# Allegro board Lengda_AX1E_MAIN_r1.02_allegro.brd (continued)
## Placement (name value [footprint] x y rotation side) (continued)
PC68  10UF  [CC0603N]  176.43 94.46 315 top
PC69  4.7UF  [CC0603N]  95.68 88.14 0 top
PCP2  47uF  [CAE660W800HN]  167.18 111.65 90 top
PR1  0  [RC0603N]  198.93 105.7 180 top
PR2  1.1K  [RC0402N]  225.47 112.56 90 bottom
PR3  0  [RC0402N]  219.22 106.13 180 bottom
PR4  2.2  [RC0603N]  230.4 105.34 0 bottom
PR5  10k  [RC0402N]  196.62 106.59 0 top
PR6  10k  [RC0402N]  219.23 105.35 180 bottom
PR7  110K  [RC0402N]  223.54 91.15 270 bottom
PR8  6.2K  [RC0402N]  224.3 91.15 270 bottom
PR9  30K  [RC0402N]  225.29 91.28 270 bottom
PR10  2.2  [RC0603N]  208.49 103.12 180 bottom
PR11  0  [RC0402N]  208.57 105.26 180 bottom
PR12  2.2  [RC0603N]  203.51 106.36 180 bottom
PR13  100  [RC0402N]  154.29 44.92 180 bottom
PR14  2.2  [RC0805N]  196.63 111.68 270 top
PR15  2.2  [RC0603N]  230.55 99.16 0 bottom
PR16  0  [RC0603N]  190.63 113.81 0 top
PR17  100k  [RC0402N]  228.87 108.58 0 bottom
PR21  560  [RC0402N]  223.12 96.67 270 bottom
PR22  1k  [RC0402N]  190.72 114.8 0 top
PR24  3.9K  [RC0402N]  225.15 96.71 270 bottom
PR25  3K  [RC0402N]  223.38 108.13 90 bottom
PR26  360  [RC0402N]  224.16 96.68 270 bottom
PR28  1.1K  [RC0402N]  222.72 106.81 180 bottom
PR29  20K  [RC0402N]  160.89 79.39 180 top
PR30  20K  [RC0402N]  160.88 80.15 0 top
PR31  1.1K  [RC0402N]  222.07 108.24 270 bottom
PR32  2.2  [RC0603N]  167.06 100.07 270 bottom
PR33  16K  [RC0402N]  223.12 94.9 270 bottom
PR34  5.6K  [RC0402N]  224.15 94.88 270 bottom
PR35  22K  [RC0402N]  225.16 94.92 270 bottom
PR36  2.2  [RC0603N]  158.38 111.1 180 top
PR37  20K  [RC0402N]  162.19 79.36 270 top
PR38  10k  [RC0402N]  158.11 110 180 top
PR39  2.2  [RC0805N]  153.57 102.25 0 top
PR40  0_F  [RC0603N]  161.39 110.64 0 top
PR41  2.2  [RC0603N]  229.06 109.67 0 bottom
PR43  0  [RC0603N]  180.88 110.53 180 top
PR44  10k  [RC0402N]  179.08 110 90 top
PR45  1.1K  [RC0402N]  216.6 109.26 270 bottom
PR46  1.1K  [RC0402N]  224.44 112.42 270 bottom
PR47  2.2  [RC0805N]  177.81 104.05 0 top
PR48  0  [RC0603N]  182.48 113.36 270 top
PR49  3K  [RC0402N]  217.43 110.23 90 bottom
PR50  1k  [RC0402N]  182.2 111.61 0 top
PR51  0  [RC0402N]  214.94 104.09 180 bottom
PR52  10k  [RC0402N]  216.3 104.19 90 bottom
PR53  27K  [RC0402N]  217.87 104.19 270 bottom
PR54  1.1K  [RC0402N]  218.21 110.23 270 bottom
PR55  100  [RC0402N]  215.58 78.18 180 bottom
PR56  20K  [RC0402N]  162.97 79.37 90 top
PR57  1k  [RC0402N]  161.84 111.66 180 top
PR58  820  [RC0402N]  159.2 98.43 90 bottom
PR59  100  [RC0402N]  218.75 101.61 0 bottom
PR60  120  [RC0402N]  157.58 98.42 270 bottom
PR61  0  [RC0402N]  161.91 101.95 270 bottom
PR62  10k  [RC0402N]  160.01 101.73 270 bottom
PR63  10k  [RC0402N]  157.78 102.86 0 bottom
PR64  100  [RC0402N]  161.11 101.95 270 bottom
PR65  0  [RC0603N]  210.97 114.35 270 top
PR66  0  [RC0402N]  164.19 99.71 270 bottom
PR67  10k  [RC0402N]  210.97 112.61 180 top
PR68  10k  [RC0402N]  230.76 106.38 180 bottom
PR69  100  [RC0402N]  163.4 99.71 90 bottom
PR70  100  [RC0402N]  214.94 103.32 180 bottom
PR71  100  [RC0402N]  154.61 55.8 270 bottom
PR72  75  [RC0402N]  66.87 77.48 270 bottom
PR73  2.2  [RC0805N]  208.3 104.06 90 top
PR74  0  [RC0603N]  212.76 113.63 270 top
PR75  75  [RC0402N]  67.75 82.66 90 bottom
PR76  75  [RC0402N]  67.66 77.49 270 bottom
PR77  10k  [RC0402N]  221.64 97.68 180 bottom
PR78  2.2  [RC0603N]  230.38 102.87 180 bottom
PR79  3K  [RC0402N]  223.65 112.43 270 bottom
PR80  1k  [RC0402N]  213.75 113.92 270 top
PR81  3.9  [RC0402N]  218.75 100.82 0 bottom
PR83  100  [RC0402N]  212.4 78.15 180 bottom
PR92  0_F  [RC0603N]  111.63 57.86 90 bottom
PR93  10k  [RC0402N]  227.95 98.93 180 bottom
PR94  15K  [RC0402N]  225.68 110.91 0 bottom
PR95  110K  [RC0402N]  225.49 107.5 180 bottom
PR96  100K_NTC  [RC0402N]  201.32 105.79 0 top
PR97  18K  [RC0402N]  225.52 108.28 180 bottom
PR98  6.8  [RC0603N]  218.16 98.41 0 bottom
PR100  100K_NTC  [RC0402N]  188.16 101.76 90 top
PR101  8.06K  [RC0402N]  216.95 99.62 180 bottom
PR102  10k  [RC0402N]  216.94 100.55 180 bottom
PR103  12.7K  [RC0402N]  215.63 100.14 270 bottom
PR106  0  [RC0402N]  218.76 102.39 180 bottom
PR107  1k  [RC0402N]  44.91 13.36 90 bottom
PR108  6.34K  [RC0402N]  158.7 101.23 0 bottom
PR109  0  [RC0402N]  223.2 93.11 270 bottom
PR110  360  [RC0402N]  224.2 93.11 270 bottom
PR111  2.2K  [RC0402N]  225.16 93.11 270 bottom
PR112  0  [RC0402N]  219.19 103.39 0 bottom
PR113  0  [RC0402N]  218.75 100.04 180 bottom
PR114  100_R  [RC0402N]  225.19 109.59 90 bottom
PR115  150  [RC0402N]  226 109.62 270 bottom
PR116  0  [RC0402N]  160.02 97.06 180 bottom
PR117  0  [RC0402N]  160.49 97.97 180 bottom
PR118  82  [RC0402N]  158.19 97.1 0 bottom
PR119  1k  [RC0402N]  165.3 103.6 0 top
PR120  1k  [RC0402N]  35.19 15.75 180 bottom
PU3  RT9610CQW  [DFN50P200X200-8CN]  205.7 104.5 180 bottom
Q1  SM2300NSANC  [SOT95P280-3N]  62.7 87.17 180 bottom
Q2  SM2300NSANC  [SOT95P280-3N]  62.7 90.53 180 bottom
Q4  BSS138  [SOT95P280-3N]  106.02 51.19 0 bottom
Q5  SM4370  [SOIC127P605X520-8N]  200.96 109.24 0 top
Q6  SM4373  [SOIC127P605X520-8N]  192.83 109.68 270 top
Q7  2N7002LT1  [SOT95P240-3N]  153.46 47.84 270 bottom
Q8  SM4370  [SOIC127P605X520-8N]  175.23 108.57 180 top
Q9  SM4373  [SOIC127P605X520-8N]  186 109.67 270 top
Q10  2N7002LT1  [SOT95P240-3N]  153.27 52.09 90 bottom
Q11  SM2300NSANC  [SOT95P280-3N]  52.08 84.84 270 bottom
Q12  2N7002LT1  [SOT95P240-3N]  52.19 72.43 90 top
Q13  2N7002LT1  [SOT95P240-3N]  48.81 72.43 90 top
Q14  LBSS138LT1G  [SOT95P240-3N]  61.53 81.99 90 top
Q15  2N7002LT1  [SOT95P240-3N]  148.92 56.97 0 top
Q17  AON3419  [DFN65P280X290-8N]  97.58 108.62 90 top
Q18  BSS138  [SOT95P280-3N]  148.7 53.57 180 top
Q19  2N7002LT1  [SOT95P240-3N]  156.46 70.26 0 top
Q22  SM4370  [SOIC127P605X520-8N]  153.6 106.15 180 top
Q23  SM4373  [SOIC127P605X520-8N]  160.92 106.56 180 top
Q27  2N7002LT1  [SOT95P240-3N]  156.46 73.6 0 top
Q29  SM4370  [SOIC127P605X520-8N]  207.82 109.25 180 top
Q30  2N7002LT1  [SOT95P240-3N]  95.52 109.03 270 bottom
Q31  2N7002LT1  [SOT95P240-3N]  83.47 107.56 90 top
Q32  SM4373  [SOIC127P605X520-8N]  214.36 108.74 270 top
Q34  APM1105NUCT-TRG  [SOT229P990-3N]  65.88 37.04 270 top
Q36  sc-70  [SOT65P210-3N]  121.46 113.07 90 top
Q40  SM2300NSANC  [SOT95P280-3N]  112.74 59.13 90 top
Q41  BSS138  [SOT95P280-3N]  35.1 56.55 90 top
Q42  2N7002LT1  [SOT95P240-3N]  65.09 22.63 180 bottom
Q44  2N7002LT1  [SOT95P240-3N]  34.61 60.7 90 top
Q48  L2N7002LT1G  [SOT_23_M]  43.86 87.1 270 bottom
Q49  LMBT3904LT1G  [SOT_23_M]  39.99 86.97 180 bottom
Q56  APM3302QA  [SON65P330X330-8N]  122.09 71.16 90 bottom
Q68  APM3302QA  [SON65P330X330-8N]  88.65 73.07 90 top
Q69  2N7002LT1  [SOT95P240-3N]  116.77 65.63 90 bottom
Q71  2N7002LT1  [SOT95P240-3N]  120.12 65.63 270 bottom
Q72  DTC144EUA  [SOT65P210-3N]  231.54 17.53 0 top
Q74  APM3302QA  [SON65P330X330-8N]  122.85 76.2 90 bottom
Q76  2N7002LT1  [SOT95P240-3N]  117.95 77.48 270 bottom
Q77  2N7002LT1  [SOT95P240-3N]  80.09 73.85 90 top
Q78  2N7002LT1  [SOT95P240-3N]  144.23 60.01 270 bottom
Q79  2N7002LT1  [SOT95P240-3N]  80.09 69.94 90 top
Q80  2N7002LT1  [SOT95P240-3N]  84.74 70.38 270 top
Q81  2N7002LT1  [SOT95P240-3N]  128.73 64.87 180 bottom
Q83  2N7002LT1  [SOT95P240-3N]  105.88 54.59 0 bottom
Q84  2N7002LT1  [SOT95P240-3N]  150.14 87.11 0 bottom
Q85  2N7002LT1  [SOT95P240-3N]  231.65 100.83 270 top
Q86  2N7002LT1  [SOT95P240-3N]  117.58 72.42 90 bottom
Q88  2N7002LT1  [SOT95P240-3N]  143.96 92.83 270 bottom
R1  2.2  [RC0603N]  118.31 53.85 0 bottom
R3  100k  [RC0402N]  176.37 63.28 90 bottom
R4  0  [RC0402N]  129.14 102.81 0 top
R5  10_F  [RC0603N]  144.21 97.29 90 top
R6  2.2  [RC0603N]  145.82 102.07 180 top
R7  10k  [RC0402N]  172.19 82.07 270 bottom
R8  100k  [RC0402N]  161.88 70.61 270 top
R9  2.2K  [RC0402N]  157.21 79.09 180 top
R10  2.2K  [RC0402N]  157.21 78.32 180 top
R11  0  [RC0402N]  153.3 79.95 0 top
R12  100k  [RC0402N]  158.76 69.26 270 top
R13  0_F  [RC0603N]  47.78 83.48 270 bottom
R14  0  [RC0402N]  31.69 53.36 90 bottom
R15  0  [RC0402N]  39.93 80.87 90 bottom
R16  100k  [RC0402N]  161.1 70.61 270 top
R17  200K  [RC0402N]  165.19 83.74 0 top
R18  150  [RC0402N]  197.9 88.04 0 top
R19  100k  [RC0402N]  170.1 57.28 0 bottom
R20  60.4  [RC0402N]  168.79 88.52 90 top
R21  10M  [RC0402N]  171.14 59.27 90 bottom
R22  1k  [RC0402N]  165.12 59.68 0 top
R23  150  [RC0402N]  209.51 85.6 0 bottom
R24  0  [RC0402N]  153.29 80.73 0 top
R25  20K  [RC0402N]  166.38 64.78 180 bottom
R26  33_R  [RC0402N]  152.55 54.26 0 top
R27  20K  [RC0402N]  166.09 58.14 270 bottom
R28  100k  [RC0402N]  175.59 63.29 90 bottom
R29  0  [RC0402N]  66.95 82.66 90 bottom
R30  100k  [RC0402N]  163.25 71.2 0 top
R31  100k  [RC0402N]  165.14 57.69 0 top
R32  100_R  [RC0402N]  227.44 94.49 270 bottom
R33  10_F  [RC0603N]  88.51 87.81 180 top
R34  10k  [RC0402N]  93.38 89.74 270 top
R35  10_F  [RC0603N]  126.16 79.71 270 top
R36  100k  [RC0402N]  125.85 77.31 270 top
R37  10k  [RC0402N]  121.14 77.31 90 top
R38  2.2  [RC0603N]  123.94 75.81 0 top
R39  13.7K  [RC0402N]  122.74 77.31 90 top
R40  61.9k  [RC0402N]  124.29 77.31 270 top
R41  49.9  [RC0402N]  207.38 84.74 90 bottom
R42  1.8K  [RC0603N]  197.91 20.28 180 bottom
R43  2  [RC0402N]  218.24 63.69 180 bottom
R44  0  [RC0402N]  218.45 55.15 90 bottom
R45  2  [RC0402N]  215.67 65.19 0 bottom
R46  0  [RC0603N]  153.32 57.28 90 bottom
R47  0  [RC0603N]  152.07 57.28 90 bottom
R48  0_F  [RC0603N]  58.24 72.87 180 bottom
R49  2.2K  [RC0402N]  155.44 79.56 90 top
R50  0  [RC0603N]  169.09 69.12 0 bottom
R51  0  [RC0603N]  169.02 70.37 0 bottom
R52  0  [RC0603N]  167.9 75.24 0 bottom
R53  0  [RC0603N]  167.1 78.77 0 bottom
R54  100k  [RC0402N]  175.71 68.63 90 bottom
R55  270K  [RC0402N]  114.55 57.38 270 bottom
R56  1k  [RC0402N]  112.62 57.38 90 bottom
R57  2.2K  [RC0402N]  155.44 77.77 270 top
R58  2.2K  [RC0402N]  164.05 78.56 270 top
R59  0_F  [RC0603N]  220.63 32.26 0 bottom
R62  0  [RC0402N]  220.91 33.27 180 bottom
R65  49.9  [RC0402N]  226.03 95.12 90 bottom
R66  0  [RC0402N]  177.44 74.39 90 bottom
R67  100_R  [RC0402N]  169.57 88.52 90 top
R68  0  [RC0402N]  179.22 57.29 225 top
R69  100k  [RC0402N]  165.14 58.87 0 top
R70  100k  [RC0402N]  110.92 56.07 180 bottom
R71  1M  [RC0402N]  165.92 65.61 0 bottom
R72  10k  [RC0402N]  165.85 69.2 180 top
R73  10k  [RC0402N]  165.76 80.61 180 top
R74  0  [RC0402N]  209.21 68.53 180 bottom
R75  100_R  [RC0402N]  219.73 61.86 180 top
R76  100_R  [RC0402N]  219.74 60.99 180 top
R77  100_R  [RC0402N]  219.7 62.57 180 top
R78  10k  [RC0402N]  165.84 69.98 180 top
R79  100_R  [RC0402N]  58.16 71.82 0 bottom
R80  49.9  [RC0402N]  183.48 66.26 270 bottom
R81  24.9  [RC0402N]  216.62 62.41 90 bottom
R82  0  [RC0402N]  42.61 80.1 90 bottom
R83  0  [RC0402N]  157.19 66.17 180 top
R84  10k  [RC0402N]  58.54 68.54 180 bottom
R85  49.9  [RC0402N]  167.99 88.53 90 top
R86  10k  [RC0402N]  58.54 67.74 180 bottom
R87  24.9  [RC0402N]  215.67 66.79 0 bottom
R88  10k  [RC0402N]  49.12 80.66 270 bottom
R90  0  [RC0402N]  40.18 58.74 270 bottom
R91  0  [RC0402N]  42.33 58.86 270 bottom
R92  10k  [RC0402N]  163.3 75.72 180 top
R93  100k  [RC0402N]  165.13 62.19 0 top
R94  100k  [RC0402N]  165.75 60.81 270 bottom
R96  0  [RC0402N]  176.95 76.59 270 bottom
R97  10k  [RC0402N]  165.14 56.88 0 top
R98  1k  [RC0402N]  184.01 90.09 270 top
R99  100k  [RC0402N]  178.32 70.74 270 bottom
R101  0  [RC0402N]  169.36 62.42 0 bottom
R102  60.4  [RC0402N]  184.81 90.1 270 top
R103  0  [RC0402N]  175.61 60.24 225 top
R104  4.7K  [RC0402N]  169.02 59.45 90 bottom
R105  10k  [RC0402N]  49.91 80.66 270 bottom
R106  1k  [RC0402N]  193.16 89.59 270 top
R107  4.7K  [RC0402N]  168.21 59.44 270 bottom
R108  100k  [RC0402N]  162.75 57.47 180 top
R109  1M  [RC0402N]  110.92 55.06 180 bottom
R110  100k  [RC0402N]  170.84 77.32 0 bottom
R111  100k  [RC0402N]  158.33 77.38 0 top
R112  0  [RC0402N]  110.92 54.29 0 bottom
R113  33_R  [RC0402N]  50.85 86.41 0 top
R114  1k  [RC0402N]  205.08 85.22 90 bottom
R115  10k  [RC0402N]  51.73 70.08 0 top
R116  10k  [RC0402N]  49.93 70.08 180 top
R117  0  [RC0402N]  110.92 51.96 180 bottom
R118  0  [RC0402N]  110.92 52.73 180 bottom
R119  100k  [RC0402N]  48.07 70.08 180 top
R120  0  [RC0402N]  110.92 53.51 180 bottom
R121  20K  [RC0402N]  112.89 50.29 90 bottom
R122  1k  [RC0402N]  218.89 85.84 0 bottom
R123  12K  [RC0603N]  111.13 49.82 180 bottom
R124  1k  [RC0402N]  219.19 88.69 270 top
R125  0  [RC0402N]  181.76 58.87 225 top
R126  0  [RC0402N]  58.54 69.32 180 bottom
R127  2.2  [RC0603N]  109.15 49.97 270 bottom
R128  0_F  [RC0603N]  206.65 32.22 0 bottom
R129  49.9  [RC0402N]  215.81 88.8 270 top
R130  0  [RC0402N]  58.54 66.95 180 bottom
R131  51  [RC0402N]  213.9 88.94 90 top
R132  51  [RC0402N]  210.88 85.99 270 bottom
R133  51  [RC0402N]  215.58 90.65 90 top
R134  0  [RC2512N]  97.46 108.48 90 top
R135  51  [RC0402N]  210.56 84.53 0 bottom
R137  51  [RC0402N]  214.79 88.81 90 top
R138  10k  [RC0402N]  51.05 80.74 270 bottom
R139  100k  [RC0402N]  162 98.04 90 bottom
R140  10k  [RC0402N]  51.84 80.74 270 bottom
R141  51  [RC0402N]  214.55 90.75 90 top
R142  0  [RC0402N]  182.21 57.88 225 top
R143  0  [RC0402N]  180.57 56.99 225 top
R144  0  [RC0402N]  181.2 56.36 225 top
R145  0  [RC0402N]  143.29 86.06 0 top
R146  1k  [RC0402N]  197.34 89.59 270 top
R147  1k  [RC0402N]  198.93 89.59 270 top
R148  1k  [RC0402N]  198.12 89.59 90 top
R149  1k  [RC0402N]  194.08 89.59 270 top
R150  0  [RC0402N]  163.09 60.16 180 top
R151  499  [RC0402N]  218.91 86.67 180 bottom
R153  51  [RC0402N]  208.87 90.36 270 bottom
R154  100k  [RC0402N]  177.89 63.45 90 bottom
R155  33_R  [RC0402N]  53.4 86.42 0 top
R156  100k  [RC0402N]  164.18 82.29 0 top
R157  0  [RC0402N]  57.77 76.22 180 top
R158  0  [RC0402N]  129.14 102.02 0 top
R159  1k  [RC0402N]  194.96 89.59 90 top
R160  10k  [RC0402N]  163.25 70.41 180 top
R161  0  [RC0402N]  129.14 101.02 0 top
R162  10k  [RC0402N]  165.85 70.91 0 top
R163  200  [RC0402N]  165.87 71.75 0 top
R164  0  [RC0402N]  129.14 100.17 0 top
R165  10k  [RC0402N]  58.55 70.9 180 bottom
R166  0  [RC0402N]  129.14 99.38 0 top
R167  0_F  [RC0603N]  206.66 33.45 0 bottom
R168  100_R  [RC0402N]  47.82 79.97 270 bottom
R169  1k  [RC0402N]  191.58 89.58 270 top
R170  390K  [RC0603N]  88.68 108.89 0 top
R171  100  [RC1206N]  94.46 113.41 0 top
R172  10k  [RC0603N]  85.72 108.64 90 top
R173  0  [RC0402N]  169.05 72.25 180 bottom
R174  1M  [RC0402N]  90.47 108.42 270 top
R175  249K  [RC0402N]  174.12 66.98 270 bottom
R176  1k  [RC0402N]  175.17 65.49 270 bottom
R177  10k  [RC0402N]  160.53 78.11 90 top
R178  1k  [RC0402N]  211.22 80.95 0 bottom
R179  10k  [RC0402N]  158.33 76.61 180 top
R180  4.7K  [RC0402N]  158.32 75.78 0 top
R181  20K  [RC0402N]  127.25 101.3 180 top
R182  100K  [RC0402N]  212.25 11.22 0 bottom
R183  100K  [RC0402N]  212.25 12.01 180 bottom
R184  0_F  [RC0603N]  142.87 75.72 270 top
R185  0  [RC0402N]  212.25 12.79 180 bottom
R186  0  [RC0402N]  144.38 78.24 270 top
R187  34K  [RC0402N]  222.45 11.7 90 bottom
R188  0  [RC0402N]  143.09 78.75 180 top
R190  20K  [RC0402N]  61.98 90.28 0 top
R191  20k  [RC0603N]  144.3 81.76 90 top
R192  100K  [RC0402N]  158.33 56.33 90 bottom
R193  1.8K  [RC0603N]  202.6 20.23 180 bottom
R194  10k  [RC0402N]  150.01 100.24 270 top
R195  0_H  [RC0805N]  208.15 8.55 180 bottom
R196  100k  [RC0402N]  116.67 67.93 0 bottom
R197  0  [RC0402N]  76.82 61.13 270 bottom
R198  100k  [RC0402N]  72.77 63.23 270 bottom
R199  0  [RC0402N]  58.15 64.43 180 bottom
R200  100  [RC0402N]  123.6 114.19 180 top
R201  680  [RC0402N]  59.06 82.31 90 top
R202  680  [RC0402N]  57.86 82.31 90 top
R203  100k  [RC0402N]  116.8 63.19 0 bottom
R204  100k  [RC0402N]  143.5 100.25 90 top
R205  10k  [RC0402N]  149.24 100.24 270 top
R206  0  [RC0402N]  148.19 100.25 90 top
R207  10k  [RC0402N]  43.11 58.86 90 bottom
R208  20K  [RC0402N]  145.8 100.25 90 top
R209  33_R  [RC0402N]  55.94 86.4 0 top
R210  10k  [RC0402N]  111.43 61.66 180 top
R211  15K  [RC0402N]  145.03 100.25 90 top
R212  0  [RC0402N]  174.11 72.22 90 bottom
R213  60.4  [RC0402N]  129.14 104.42 0 top
R214  33_R  [RC0402N]  149.95 50.56 0 top
R215  0  [RC0402N]  147.08 80.73 270 top
R216  0  [RC0402N]  181.52 61.73 270 bottom
R217  33_R  [RC0402N]  58.42 86.41 0 top
R218  0_F  [RC0603N]  69.16 61.86 90 bottom
R219  0_F  [RC0603N]  21.3 44.65 180 bottom
R220  10k  [RC0603N]  143.53 79.77 0 top
R221  0  [RC0402N]  220.34 36.02 0 bottom
R222  1k  [RC0402N]  179.86 44.19 270 bottom
R223  0  [RC0402N]  96.84 60.97 0 top
R224  100_R  [RC0402N]  218.28 84.17 270 bottom
R225  16k  [RC0603N]  221.37 11.97 270 bottom
R226  150  [RC0402N]  170.71 65.54 45 bottom
R227  0  [RC0402N]  93.87 91.13 180 top
R228  0  [RC0402N]  93.88 91.92 180 top
R229  240  [RC0402L]  192.21 18.21 270 bottom
R231  0  [RC0402N]  180.08 60.24 180 bottom
R232  10k  [RC0402N]  15.08 112.35 270 top
R233  0  [RC0402N]  181.18 64.02 270 bottom
R234  100K  [RC0402N]  148.41 81.26 0 top
R235  49.9  [RC0402N]  226.03 96.9 270 bottom
R236  10k  [RC0402N]  203.33 18.61 270 bottom
R237  43R  [RC0402N]  56.75 68.69 90 top
R238  100k  [RC0402N]  47.63 58.97 270 bottom
R239  0  [RC0402N]  227.43 96.27 270 bottom
R240  10k  [RC0402N]  127.21 93.79 180 top
R241  10k  [RC0402N]  221.95 20.15 180 bottom
R242  0  [RC0402N]  228.34 95.71 270 bottom
R243  0  [RC0402N]  73.02 65.94 90 bottom
R244  0  [RC0402N]  127.93 94.46 45 bottom
R245  0  [RC0402N]  120.63 89.23 90 bottom
R246  100k  [RC0402N]  124.19 87.61 180 bottom
R247  1k  [RC0402N]  74.3 65.67 0 bottom
R248  10k  [RC0402N]  125.32 95.02 90 bottom
R249  680  [RC0402N]  56.54 82.31 90 top
R250  1k  [RC0402N]  196.57 89.59 270 top
R251  680  [RC0402N]  55.34 82.31 90 top
R252  100k  [RC0402N]  152.35 56.78 0 top
R253  680  [RC0402N]  54.01 82.31 90 top
R254  680  [RC0402N]  52.8 82.31 90 top
R255  680  [RC0402N]  51.54 82.31 90 top
R256  0_F  [RC0603N]  21.3 45.87 180 bottom
R257  680  [RC0402N]  50.27 82.31 90 top
R258  1k  [RC0402N]  49.99 83.75 90 bottom
R259  0  [RC0402N]  229.12 95.72 270 bottom
R260  10k  [RC0402N]  152.34 55.04 180 top
R261  2K  [RC1206N]  88.64 106.46 0 top
R262  0_F  [RC0603N]  11.44 112.92 180 top
R263  0  [RC0402N]  129.1 97.22 0 top
R264  0  [RC0402N]  129.1 96.41 0 top
R265  0_F  [RC0603N]  11.39 110.94 180 top
R266  33_R  [RC0402N]  152.34 56.01 0 top
R267  0_F  [RC0603N]  224.6 112.7 270 top
R268  0_F  [RC0603N]  225.81 112.7 270 top
R269  15K  [RC0402N]  74.3 66.44 0 bottom
R270  1k  [RC0402N]  204.3 85.22 90 bottom
R271  0_F  [RC0603N]  21.3 48.37 180 bottom
R272  0_F  [RC0603N]  21.3 47.14 180 bottom
R273  0  [RC0402N]  112.31 59.18 45 top
R274  0  [RC0402N]  129.1 95.63 0 top
R275  0  [RC0402N]  129.1 94.86 0 top
R276  100k  [RC0402N]  127.21 94.55 180 top
R277  33_R  [RC0402N]  152.35 52.71 0 top
R278  33_R  [RC0402N]  152.35 57.58 0 top
R279  200  [RC0402N]  183.44 64.06 45 bottom
R280  100k  [RC0402N]  186.49 89.44 90 top
R281  0  [RC0402N]  128.97 92.57 0 top
R282  200  [RC0402N]  178.9 68.08 225 bottom
R283  1k  [RC0402N]  199.69 89.59 270 top
R284  0  [RC0402N]  161.48 72.53 180 top
R285  10k  [RC0402N]  202.56 18.61 270 bottom
R286  0  [RC0402N]  163.27 71.98 180 top
R287  0  [RC0402N]  163.27 72.85 180 top
R288  100k  [RC0402N]  185.68 89.43 90 top
R289  10k  [RC0402N]  223.26 19.68 270 bottom
R290  10k  [RC0402N]  223.27 17.86 90 bottom
R291  240  [RC0402L]  182.37 17.44 90 bottom
R292  10k  [RC0402N]  222.8 16.52 180 bottom
R293  240  [RC0402L]  181.76 13.78 90 bottom
R294  240  [RC0402L]  184.32 12.72 90 bottom
R295  240  [RC0402L]  184.87 15.48 270 bottom
R296  240  [RC0402L]  180.92 19.49 270 bottom
R297  240  [RC0402L]  179.63 13.89 90 bottom
R298  240  [RC0402L]  183.65 20.35 270 bottom
R299  240  [RC0402L]  184.98 18.26 180 bottom
R300  470  [RC0402N]  182.34 22.75 180 bottom
R301  0  [RC0402N]  182.34 23.53 0 bottom
R302  240  [RC0402L]  183.52 12.94 270 bottom
R303  240  [RC0402L]  182.58 13.78 270 bottom
R304  0  [RC0402N]  221.65 96.88 180 bottom
R305  100_R  [RC0402N]  215.36 86.46 270 bottom
R306  56  [RC0402N]  213 85.13 0 bottom
R307  0  [RC0402N]  213 85.91 0 bottom
R309  100k  [RC0402N]  166.04 99.9 270 bottom
R310  100k  [RC0402N]  166.38 90.74 270 bottom
R311  1k  [RC0402N]  165.25 65.19 0 top
R312  1k  [RC0402N]  165.25 65.97 0 top
R313  10k  [RC0402N]  165.58 90.74 90 bottom
R314  0_F  [RC0603N]  45.54 88.52 90 top
R315  0_F  [RC0603N]  144.15 49.45 270 top
R316  100k  [RC0402N]  163.86 90.72 270 bottom
R317  10k  [RC0402N]  164.65 90.72 90 bottom
R318  10k  [RC0402N]  165.54 92.91 90 bottom
R319  0  [RC0402N]  135.11 61.39 0 bottom
R320  0  [RC0402N]  135.11 60.61 0 bottom
R321  2.2  [RC0603N]  170.03 97.58 270 bottom
R322  100k  [RC0402N]  43.4 80.08 90 bottom
R323  10k  [RC0402N]  165.13 61.38 0 top
R324  10k  [RC0402N]  162.74 56.68 180 top
R325  10k  [RC0402N]  44.47 58.95 90 bottom
R326  10k  [RC0402N]  164.67 92.9 90 bottom
R327  0  [RC0402N]  163.7 92.87 90 bottom
R328  0  [RC0402N]  228.87 107.79 0 bottom
R329  2.2  [RC0603N]  161.29 93.22 180 bottom
R330  0  [RC0402N]  44.02 73.37 90 top
R331  0  [RC0402N]  113.37 65.72 270 top
R332  1k  [RC0402N]  208.15 80.64 90 bottom
R333  1k  [RC0402N]  202.56 80.02 270 bottom
R334  0  [RC0402N]  135.19 56.5 0 bottom
R335  100k  [RC0402N]  58.13 65.23 180 bottom
R336  1k  [RC0402N]  192.35 89.59 270 top
R337  0  [RC0402N]  114.15 65.72 270 top
R338  10k  [RC0402N]  110.67 57.88 90 top
R339  10k  [RC0402N]  38.62 58.22 90 bottom
R340  0  [RC0402N]  230.76 107.16 0 bottom
R341  1k  [RC0402N]  204.92 80.97 180 bottom
R343  1k  [RC0402N]  195.8 89.59 270 top
R344  0  [RC0402N]  135.19 55.72 0 bottom
R345  10k  [RC0402N]  41.57 58.86 90 bottom
R346  1k  [RC0402N]  162.29 67.61 0 top
R347  1k  [RC0402N]  162.29 66.84 0 top
R349  10k  [RC0402N]  55.77 82.13 90 bottom
R350  10k  [RC0402N]  56.25 83.43 0 bottom
R351  100k  [RC0402N]  72.23 65.94 270 bottom
R352  10k  [RC0402N]  58.48 63.06 90 bottom
R353  0  [RC0402N]  158.14 55.06 0 bottom
R354  0  [RC0402N]  159.37 56.88 270 bottom
R355  10k  [RC0402N]  57.58 63.07 270 bottom
R356  0  [RC0402N]  55.31 60.74 180 bottom
R357  0_F  [RC0603N]  161.72 92.62 270 top
R358  0_F  [RC0603N]  77.1 64.92 270 bottom
R359  10k  [RC0402N]  45.92 74.11 90 top
R360  10k  [RC0402N]  44.57 77.14 0 top
R361  10k  [RC0402N]  46.7 74.11 270 top
R362  0  [RC0402N]  78.51 62.47 180 bottom
R363  0_F  [RC0603N]  66.32 64.16 180 bottom
R364  1k  [RC0402N]  113.21 61.66 180 top
R365  0  [RC0402N]  155.52 88.22 90 top
R366  1k  [RC0402N]  201.72 80.03 270 bottom
R367  1k  [RC0402N]  200.94 80.03 270 bottom
R368  0  [RC0402N]  134.61 62.69 90 bottom
R369  10k  [RC0402N]  181.55 54.65 0 bottom
R370  10k  [RC0402N]  181.56 56.19 0 bottom
R371  0  [RC0402N]  36.74 61.45 90 top
R372  10k  [RC0402N]  44.57 77.92 180 top
R373  100k  [RC0402N]  219.19 90.53 90 top
R374  10k  [RC0402N]  161.32 78.11 90 top
R375  316K  [RC0603N]  161.33 95.67 0 bottom
R376  1k  [RC0402N]  203.32 80.02 270 bottom
R377  100k  [RC0402N]  168.41 61.3 0 bottom
R378  0  [RC0402N]  151.59 99.97 270 top
R379  10k  [RC0402N]  166.06 72.61 0 bottom
R380  10k  [RC0402N]  36.73 65.11 270 top
R381  100k  [RC0402N]  157.21 66.96 0 top
R382  100k  [RC0402N]  174.22 58.83 225 top
R383  100k  [RC0402N]  172.09 62.2 180 bottom
R384  100k  [RC0402N]  171.44 55.81 225 top
R385  10k  [RC0402N]  36.74 63.23 270 top
R386  10k  [RC0402N]  32.59 60.17 270 top
R387  100k  [RC0402N]  165.14 60.59 180 top
R388  100k  [RC0402N]  177.28 66.82 90 bottom
R389  100k  [RC0402N]  25.43 82.49 270 top
R390  1K  [RC0402N]  36.74 59.61 90 top
R391  4.7K  [RC0402N]  23.18 79.28 0 top
R392  4.7K  [RC0402N]  23.18 80.05 0 top
R393  0_F  [RC0603N]  31.79 87.74 90 top
R394  0  [RC0402N]  135.11 59.87 0 bottom
R395  1k  [RC0402N]  32.1 90.89 90 top
R396  100k  [RC0402N]  39.92 84.88 180 top
R397  0  [RC0402N]  33.93 75.83 90 top
R398  200K  [RC0402N]  39.92 85.66 180 top
R399  1k  [RC0402N]  35.12 71.62 180 top
R400  3.3k  [RC0402N]  36.27 84.74 180 top
R401  3.3k  [RC0402N]  37.64 84.89 270 top
R404  20K  [RC0402N]  166.06 73.4 180 bottom
R405  100k  [RC0402N]  159.07 79.74 90 top
R406  0  [RC0402N]  35.43 77.31 180 top
R407  22  [RC0402N]  35.43 78.1 0 top
R408  100k  [RC0402N]  35.6 78.87 180 top
R409  1k  [RC0402N]  37.54 76.56 90 bottom
R410  1k  [RC0402N]  36.46 76.56 90 bottom
R411  100k  [RC0402N]  62.3 12.63 0 bottom
R412  100k  [RC0402N]  152.62 46.67 0 top
R414  33_R  [RC0402N]  151.74 50.09 0 top
R415  75k  [RC0402N]  130.05 106.39 270 top
R416  33_R  [RC0402N]  149.96 51.45 0 top
R417  33_R  [RC0402N]  151.74 51 0 top
R418  2.2K  [RC0402N]  17.01 89.67 270 top
R419  2.2K  [RC0402N]  9.06 90.75 0 bottom
R420  10k  [RC0402N]  125.52 103.37 180 top
R421  0  [RC0402N]  220.34 38 180 bottom
R422  0  [RC0402N]  161.25 60.13 0 top
R423  33  [RC0603N]  20.07 82.54 90 top
R424  0_F  [RC0603N]  22.13 104.61 180 bottom
R425  33  [RC0603N]  21.29 82.54 90 top
R426  0  [RC0402N]  220.34 39.81 180 bottom
R427  0_F  [RC0603N]  22.13 103.38 180 bottom
R428  0_F  [RC0603N]  24.02 94.07 90 bottom
R429  0_F  [RC0603N]  22.77 94.07 90 bottom
R430  0_F  [RC0603N]  21.52 94.07 90 bottom
R431  0_F  [RC0603N]  20.27 94.07 90 bottom
R432  0  [RC0402N]  135.19 54.93 0 bottom
R433  10  [RC0402N]  149.95 47.66 0 top
R434  10  [RC0402N]  151.72 48.09 0 top
R435  10  [RC0402N]  149.94 48.57 0 top
R436  10  [RC0402N]  151.73 49.08 0 top
R437  49.9  [RC0402N]  149.93 49.59 180 top
R438  1k  [RC0402N]  39.34 83.44 180 bottom
R439  0  [RC0402N]  163.09 59.39 180 top
R440  0  [RC0402N]  128.96 91.79 0 top
R441  0  [RC0402N]  51.78 67.53 270 top
R442  0  [RC0603N]  169.11 80.21 270 bottom
R443  10k  [RC0402N]  129.28 106.39 270 top
R444  2.2K  [RC0402N]  60.03 87.71 270 bottom
R445  2.2K  [RC0402N]  60.04 89.52 90 bottom
R446  1M  [RC0402N]  62.01 79.69 0 top
R447  0  [RC0402N]  62.01 84.31 0 top
R448  0_F  [RC0603N]  46.76 88.52 90 top
R449  1k  [RC0402N]  52.29 101.35 90 bottom
R450  0_F  [RC0603N]  50.24 84.61 90 top
R451  0_F  [RC0603N]  51.54 84.62 90 top
R452  0_F  [RC0603N]  52.75 84.6 90 top
R453  0_F  [RC0603N]  54 84.61 90 top
R454  0_F  [RC0603N]  55.25 84.62 90 top
R455  0_F  [RC0603N]  56.57 84.6 90 top
R456  0_F  [RC0603N]  57.79 84.6 90 top
R457  0_F  [RC0603N]  59.08 84.58 90 top
R462  0  [RC0402N]  129.14 98.6 180 top
R463  0  [RC0402N]  127.32 98.12 180 top
R464  0  [RC0402N]  127.32 97.36 180 top
R465  1k  [RC0402N]  119.22 69.51 180 bottom
R466  10k  [RC0402N]  127.35 99.38 180 top
R476  0  [RC0603N]  134.65 68.28 0 top
R477  0_F  [RC0603N]  32.49 102.77 180 bottom
R478  1k  [RC0402N]  41.19 107.27 0 top
R479  0_F  [RC0603N]  32.49 101.49 180 bottom
R480  0_F  [RC0603N]  34.89 94.82 90 bottom
R481  0_F  [RC0603N]  33.65 94.83 90 bottom
R482  10k  [RC0402N]  42.54 108.16 90 top
R483  0_F  [RC0603N]  32.31 93.97 90 bottom
R484  0_F  [RC0603N]  31.03 93.97 90 bottom
R485  10k  [RC0402N]  52.8 102.68 0 bottom
R488  0_F  [RC0603N]  43.27 99.78 180 bottom
R489  0_F  [RC0603N]  145.35 49.45 270 top
R490  1k  [RC0402N]  56.65 109.49 270 top
R491  0_F  [RC0603N]  43.26 98.52 180 bottom
R492  10k  [RC0402N]  57.42 109.48 90 top
R493  2.49k  [RC0603N]  68.59 75.13 270 bottom
R494  0_F  [RC0603N]  68.39 91.13 270 bottom
R495  0_F  [RC0603N]  69.65 91.13 270 bottom
R496  0_F  [RC0603N]  67.57 97.07 270 bottom
R497  0_F  [RC0603N]  66.31 97.07 270 bottom
R498  0_F  [RC0603N]  73.05 97.1 270 bottom
R499  0_F  [RC0603N]  74.3 97.1 270 bottom
R500  0_F  [RC0603N]  74.03 101.37 0 bottom
R501  75  [RC0402N]  67.98 88.5 180 top
R502  75  [RC0402N]  70 88.5 0 top
R503  75  [RC0402N]  73.92 88.48 180 top
R504  75  [RC0402N]  75.94 88.48 0 top
R505  0_F  [RC0603N]  74.03 102.62 0 bottom
R506  1  [RC0603N]  20.88 58.97 180 top
R507  100k  [RC0402N]  34.88 87.43 270 top
R508  100k  [RC0402N]  33.71 90.86 270 top
R509  0  [RC0402N]  220.34 38.98 180 bottom
R510  0  [RC0402N]  232.31 42.08 0 top
R511  0  [RC0402N]  220.33 58.64 180 bottom
R513  1k  [RC0402N]  231.23 51.15 180 top
R514  0  [RC0402N]  231.23 51.98 180 top
R515  0  [RC0402N]  232.66 48.55 0 top
R516  0  [RC0402N]  230.52 49.07 270 top
R517  10k  [RC0402N]  231.33 49.08 90 top
R518  10k  [RC0402N]  231.82 43.61 270 top
R520  430k  [RC0603N]  66.7 28.2 0 top
R521  1M  [RC0402N]  66.7 28.16 0 top
R522  0  [RC0402N]  29.57 41 0 bottom
R525  0  [RC0402N]  96.19 62.79 315 top
R526  0  [RC0402N]  93.82 62.17 270 top
R527  0  [RC0402N]  30.52 42.65 0 bottom
R529  0  [RC0402N]  29.58 41.8 0 bottom
R530  0  [RC0402N]  29.58 43.47 0 bottom
R531  1M  [RC0402N]  28.3 43.81 90 bottom
R532  10k  [RC0402N]  29.58 44.27 0 bottom
R533  100  [RC0402N]  32.75 45.8 0 bottom
R534  27K  [RC0402N]  69.46 28.21 0 top
R535  0  [RC0402N]  109.84 56.75 270 top
R536  30K  [RC0603N]  69.46 28.2 180 top
R537  100k  [RC0402N]  32.88 46.63 0 bottom
R538  51m  [RC0805N]  38.58 51.37 270 bottom
R539  51m  [RC0805N]  36.8 51.37 270 bottom
R540  0  [RC0402N]  35.88 42.18 180 bottom
R542  10k  [RC0402N]  26.52 53.58 90 bottom
R543  51m  [RC0805N]  38.67 47.89 90 bottom
R544  0  [RC0402N]  35.88 43.06 180 bottom
R545  0  [RC0402N]  26.52 51.78 270 bottom
R546  100k  [RC0402N]  32.79 53.36 270 bottom
R547  0  [RC0402N]  33.13 48.87 0 bottom
R548  100k  [RC0402N]  45.24 58.94 90 bottom
R551  51m  [RC0805N]  34.99 51.37 270 bottom
R552  0  [RC0402N]  33.1 49.71 180 bottom
R553  0  [RC0402N]  33.1 50.54 180 bottom
R554  0  [RC0402N]  33.57 53.36 90 bottom
R556  100k  [RC0402N]  24.5 51.01 180 bottom
R557  10k  [RC0402N]  230.86 15.88 0 top
R558  10k  [RC0402N]  232.84 21.96 0 top
R559  100_R  [RC0402N]  232.87 21.13 0 top
R560  4.7K  [RC0402N]  56.24 80.84 180 bottom
R561  4.7K  [RC0402N]  67 80.39 270 bottom
R562  0_F  [RC0603N]  26.95 44.29 0 top
R563  0_F  [RC0603N]  26.95 42.26 0 top
R564  0_F  [RC0603N]  26.96 40.26 0 top
R565  0_F  [RC0603N]  26.96 38.27 0 top
R566  430k  [RC0603N]  21.67 50.62 0 bottom
R567  20K  [RC0603N]  21.1 41.62 0 top
R568  18.7K  [RC0603N]  21.12 40.39 0 top
R569  10k  [RC0603N]  21.12 39.08 0 top
R570  11.3K  [RC0603N]  21.12 37.79 180 top
R571  16k  [RC0603N]  21.67 53.19 0 bottom
R572  12K  [RC0603N]  21.67 51.93 180 bottom
R573  0_H  [RC0805N]  59.47 14.76 0 bottom
R574  0_H  [RC0805N]  59.5 16.55 0 bottom
R576  10k  [RC0402N]  58.83 11.66 90 bottom
R578  1k  [RC0402N]  119.37 48.83 270 bottom
R579  0  [RC0402N]  59.59 11.66 90 bottom
R580  0  [RC0402N]  60.39 11.65 90 bottom
R581  100k  [RC0402N]  61.72 29.44 0 bottom
R582  100k  [RC0402N]  58.86 9.85 270 bottom
R583  100k  [RC0402N]  61.7 31.85 180 bottom
R584  10k  [RC0402N]  120.8 48.4 0 bottom
R585  0  [RC0402N]  26.99 43.32 180 bottom
R586  0  [RC0402N]  49.78 31.44 0 bottom
R587  0  [RC0402N]  49.78 30.66 0 bottom
R588  10k  [RC0402N]  62.7 23.65 270 bottom
R589  10k  [RC0402N]  60.44 22.38 0 bottom
R591  0_F  [RC0603N]  65.1 22.16 135 bottom
R592  100k  [RC0402N]  67.44 22.22 270 bottom
R593  0  [RC0402N]  62.28 22.05 0 bottom
R594  4.7K  [RC0402N]  47.3 24.38 180 bottom
R595  4.7K  [RC0402N]  46.18 13.87 0 bottom
R596  2k  [RC0402N]  46.05 14.66 0 bottom
R597  4.7K  [RC0402N]  50.69 17.24 270 bottom
R598  4.7K  [RC0402N]  50.7 19.46 90 bottom
R600  2k  [RC0402N]  45.41 15.8 0 bottom
R603  4.7K  [RC0402N]  49.91 17.24 270 bottom
R604  4.7K  [RC0402N]  49.9 19.46 90 bottom
R605  4.7K  [RC0402N]  46.22 12.88 0 bottom
R606  4.7K  [RC0402N]  46.1 11.61 0 bottom
R607  4.99k  [RC0402N]  48.24 19.44 90 bottom
R608  4.99k  [RC0402N]  49.02 19.44 90 bottom
R609  20K  [RC0402N]  165.93 79.64 0 top
R610  20K  [RC0402N]  180.33 63.81 90 bottom
R612  113  [RC0402N]  172.46 84.27 90 bottom
R619  0  [RC0402N]  148.91 56.5 225 top
R622  33_R  [RC0402N]  146.59 56.21 90 top
R624  10k  [RC0402N]  148.28 59.75 90 top
R627  1k  [RC0402N]  152.55 53.48 0 top
R628  1k  [RC0402N]  147.98 51.5 180 top
R629  1k  [RC0402N]  151.87 51.92 0 top
R632  2.2K  [RC0402N]  158.76 71.05 90 top
R633  2.2K  [RC0402N]  158.76 72.83 270 top
R634  10k  [RC0402N]  153.99 73.15 90 top
R635  10k  [RC0402N]  153.98 70.46 90 top
R636  499  [RC0402N]  163.6 74.45 270 top
R637  499  [RC0402N]  162.83 74.45 270 top
R644  10k  [RC0402N]  161.38 76.14 0 top
R647  2.2K  [RC0402N]  161.51 75.34 180 top
R648  2.2K  [RC0402N]  161.51 74.57 180 top
R649  100k  [RC0402N]  184.88 57.74 45 top
R650  10k  [RC0402N]  179.41 54.16 270 bottom
R653  47K  [RC0603N]  165.58 76.08 180 top
R654  47K  [RC0603N]  165.64 73.84 180 top
R655  20K  [RC0402N]  181.56 55.42 0 bottom
R664  100k  [RC0402N]  179.56 61.66 0 bottom
R665  100k  [RC0402N]  179.56 62.44 0 bottom
R679  100k  [RC0402N]  165.86 72.56 180 top
R680  100k  [RC0402N]  168.97 73.15 0 bottom
R721  3.3k  [RC0402N]  131.31 65.75 270 top
R722  3.3k  [RC0402N]  143.7 64.4 270 top
R723  3.3k  [RC0402N]  130.83 62.15 0 top
R724  33  [RC0402N]  144.21 62.32 180 top
R725  33  [RC0402N]  130.83 61.39 0 top
R726  33  [RC0402N]  144.49 64.41 270 top
R727  33  [RC0402N]  130.82 63.51 0 top
R728  33  [RC0402N]  144.17 61.4 180 top
R730  1k  [RC0402N]  202.14 33.54 0 bottom
R732  1k  [RC0402N]  204.44 32.85 270 bottom
R733  240  [RC0402L]  192.85 32.76 180 bottom
R734  10k  [RC0402N]  202.33 28.98 270 bottom
R735  10k  [RC0402N]  219.15 27.77 270 bottom
R736  10k  [RC0402N]  201.55 28.98 270 bottom
R737  10k  [RC0402N]  218.38 27.76 270 bottom
R738  10k  [RC0402N]  221.4 27.76 270 bottom
R739  240  [RC0402L]  182.3 30.58 270 bottom
R740  10k  [RC0402N]  220.6 27.76 270 bottom
R741  240  [RC0402L]  181.87 25.26 90 bottom
R742  240  [RC0402L]  184.93 24.99 90 bottom
R743  240  [RC0402L]  184.89 26.88 270 bottom
R744  240  [RC0402L]  180.81 30.78 270 bottom
R745  240  [RC0402L]  180.28 27.1 270 bottom
R746  240  [RC0402L]  185.06 30.98 180 bottom
R747  470  [RC0402N]  183.28 33.48 180 bottom
R748  240  [RC0402L]  184.95 29.76 180 bottom
R749  0  [RC0402N]  183.29 34.31 0 bottom
R750  240  [RC0402L]  183.64 24.73 0 bottom
R751  240  [RC0402L]  182.52 26.99 90 bottom
R752  100k  [RC0402N]  109.33 59.16 270 bottom
R781  680  [RC0402N]  220.5 108.24 90 bottom
R784  680  [RC0402N]  220.31 110.24 90 bottom
R785  680  [RC0402N]  227.11 112.56 90 bottom
R788  1M  [RC0402N]  118.58 63.19 180 bottom
R789  1k  [RC0402N]  92 71.43 0 top
R790  1k  [RC0402N]  118.75 67.92 0 bottom
R791  100k  [RC0402N]  119.83 75 0 bottom
R792  10k  [RC0402N]  117.49 79.81 180 bottom
R793  100K  [RC0402N]  82.18 74.66 90 top
R794  68  [RC0402N]  144.71 57.68 0 bottom
R795  100K  [RC0402N]  82.18 70.96 90 top
R796  100  [RC0603N]  85.49 67.86 0 top
R797  100  [RC0603N]  125.44 65.29 180 bottom
R799  22  [RC0402N]  108.22 54.1 270 bottom
R800  470  [RC0402N]  153.01 87.3 0 bottom
R801  47  [RC0603N]  231.04 98.22 180 top
R802  1M  [RC0402N]  82.18 72.83 90 top
R803  1M  [RC0402N]  82.18 69.08 90 top
R811  100K  [RC0402N]  82.99 105.25 180 top
R813  34K  [RC0402N]  76.42 74.07 0 top
R814  47K  [RC0603N]  76.69 75.08 180 top
R815  100k  [RC0402N]  118.05 75 180 bottom
R816  1M  [RC0402N]  117.33 70 0 bottom
R821  0_H  [RC0805N]  73.7 59.38 0 bottom
R822  1K  [RC0603N]  26.87 89.4 270 top
R823  1K  [RC0603N]  28.09 89.4 270 top
R824  1K  [RC0603N]  30.54 89.4 270 top
R825  1K  [RC0603N]  29.3 89.4 270 top
R828  10k  [RC0402N]  67.44 24 270 bottom
R829  0  [RC0402N]  39.4 58.23 270 bottom
R830  100k  [RC0402N]  153.19 60.33 135 top
R831  100k  [RC0402N]  176.36 61.91 180 bottom
R832  10k  [RC0402N]  176.7 60.53 45 bottom
R833  0_F  [RC0603N]  50.67 56.9 90 bottom
R834  0_F  [RC0603N]  51.91 56.93 90 bottom
R835  10k  [RC0402N]  58.54 70.12 180 bottom
R836  10k  [RC0402N]  41.65 84.43 180 bottom
R839  10k  [RC0402N]  171.19 63.6 0 bottom
R840  100k  [RC0402N]  44.77 57.28 180 bottom
R841  49.9  [RC0402N]  219.64 80.06 0 top
R842  49.9  [RC0402N]  219.64 80.82 0 top
R843  0  [RC0402N]  220.35 70.82 180 top
R847  150  [RC0402N]  198.31 87.13 180 bottom
R848  0  [RC0402N]  213.41 79.62 270 bottom
R849  0  [RC0402N]  211.99 79.64 270 bottom
R850  0  [RC0402N]  169.41 65.4 270 bottom
R851  0  [RC0402N]  219.64 78.51 180 top
R852  0  [RC0402N]  219.64 79.29 180 top
R855  0  [RC0603N]  188.76 87.76 270 bottom
R856  0  [RC0603N]  187.22 88.01 270 bottom
R857  100k  [RC0402N]  165.14 62.97 180 top
R858  10k  [RC0402N]  152.37 99.94 270 top
R860  100k  [RC0402N]  144.81 90.45 0 bottom
R862  100k  [RC0402N]  142.99 90.46 180 bottom
R865  4.7K  [RC0402N]  173.12 55.63 225 top
R866  4.7K  [RC0402N]  171.85 54.36 225 top
R867  1k  [RC0402N]  162.31 81 180 top
R868  1k  [RC0402N]  160.49 80.99 180 top
R870  100k  [RC0402N]  165.93 81.53 0 top
R873  20K  [RC0402N]  156.81 80.39 270 top
R874  4.7K  [RC0402N]  157.62 80.39 90 top
R875  20K  [RC0402N]  158.74 67.74 0 top
R876  4.7K  [RC0402N]  160.51 67.74 0 top
R877  0  [RC0402N]  165.24 66.74 180 top
R878  0  [RC0402N]  207.35 89.06 270 bottom
R879  0  [RC0402N]  210.22 89.87 0 bottom
R880  0  [RC0402N]  215.66 89.14 270 bottom
R881  0  [RC0402N]  214.84 89.14 270 bottom
R882  51  [RC0402N]  214.09 91.21 0 bottom
R883  0  [RC0402N]  213.22 89.09 270 bottom
R884  0  [RC0402N]  214.04 89.11 270 bottom
R885  51  [RC0402N]  213.57 90.41 0 bottom
R886  0  [RC0402N]  209.92 88.56 270 bottom
R887  0  [RC0402N]  210.7 88.56 270 bottom
R888  51  [RC0402N]  209.13 88.56 90 bottom
R889  51  [RC0402N]  211.66 85.99 270 bottom
R890  0  [RC0402N]  212.61 88.41 225 top
R891  0  [RC0402N]  212.06 88.97 225 top
R892  51  [RC0402N]  213.56 90.89 270 top
R893  0  [RC0402N]  208.2 85.59 270 bottom
R894  51  [RC0402N]  206.91 86.07 0 bottom
R895  0  [RC0402N]  160.09 51.95 0 bottom
R896  0  [RC0402N]  146.28 80.72 270 top
R897  0  [RC0402N]  95.56 89.64 270 top
R898  10k  [RC0402N]  94.79 89.64 90 top
R899  0  [RC0402N]  120.57 79.84 180 bottom
R900  0  [RC0402N]  120.57 80.63 180 bottom
R901  0  [RC0402N]  98.13 63.05 270 top
R902  100K  [RC0402N]  156.54 88.68 180 bottom
R903  0  [RC0603N]  213.45 69.97 180 bottom
R904  2.2K  [RC0402N]  165.42 77.77 180 top
R905  2.2K  [RC0402N]  165.33 80.8 270 bottom
R906  2.2K  [RC0402N]  160.13 71.35 90 top
R907  2.2K  [RC0402N]  172.89 67.04 270 bottom
R908  75k  [RC0402N]  170.36 73.11 90 bottom
R909  75k  [RC0402N]  157.09 75.45 270 bottom
R910  100K  [RC0402N]  157.79 92.38 180 bottom
R911  33  [RC0402N]  46.43 58.96 270 bottom
R916  1.8k  [RC0603N]  20.88 110.75 270 top
R917  4.7K  [RC0402N]  20.94 112.64 180 top
R918  1k  [RC0402N]  16.51 113.04 180 top
R919  1.8k  [RC0603N]  35.37 107.26 180 top
R920  4.7K  [RC0402N]  38.46 107.17 180 top
R925  1.8k  [RC0603N]  52.03 96.82 270 bottom
R926  4.7K  [RC0402N]  53.95 97.33 180 bottom
R927  20K  [RC0402N]  178.73 63.82 90 bottom
R928  20K  [RC0402N]  179.54 63.82 90 bottom
R929  1.8k  [RC0603N]  51.34 108.52 180 top
R930  4.7K  [RC0402N]  53.69 108.2 180 top
R931  1.8k  [RC0603N]  126.33 48.88 0 bottom
R932  4.7K  [RC0402N]  124.56 48.79 90 bottom
R933  100k  [RC0402N]  34.44 17.53 180 bottom
R934  100k  [RC0402N]  34.43 16.71 180 bottom
R1388  4.7K_F  [R0402]  43.56 84.42 180 bottom
R1389  100k  [RC0402N]  172.82 57.33 270 top
R1390  0  [RC0402N]  149.04 68.79 90 bottom
R1391  0  [RC0402N]  38.28 64.01 180 bottom
R1392  1M  [RC0402N]  91.32 108.44 270 top
R1393  10k  [RC0402N]  40.58 56.59 90 bottom
R1394  0  [RC0402N]  41.37 56.59 270 bottom
R1395  0  [RC0402N]  218.37 39.18 180 bottom
R1396  0  [RC0402N]  218.37 38.3 180 bottom
R1397  0  [RC0402N]  65.16 27.28 45 bottom
R1398  49.9  [RC0402N]  219.98 88.67 90 top
R1399  0  [RC0402N]  49.07 82.64 90 bottom
R1400  10k  [RC0402N]  58.55 66.17 180 bottom
SW1  THBM02  [TH-SW-420P-2N]  107.15 114.31 180 top
TP1  TP  [TEST60]  53.3 60.42 180 bottom
TP3  TP  [TEST60]  167.58 74.21 180 bottom
TP6  TP  [TEST60]  184.51 86.88 180 bottom
TP7  TP  [TEST60]  167.87 60.1 180 top
TP8  TP  [TEST60]  171.96 57.09 315 top
TP9  TP  [TEST60]  204.36 83.81 180 bottom
TP10  TP  [TEST60]  169.08 57.13 180 top
TP11  TP  [TEST60]  205.2 82.43 180 bottom
TP12  PAD~D  [TPC12]  194.76 81.21 90 bottom
TP13  PAD~D  [TPC12]  195.26 80.2 90 bottom
TP14  TP  [TEST60]  204.49 82.99 180 bottom
TP15  TP  [TEST60]  205.91 82.39 180 bottom
TP16  PAD~D  [TPC12]  195.22 81.67 90 bottom
TP17  PAD~D  [TPC12]  194.3 81.67 90 bottom
TP18  TP  [TEST60]  205.13 81.72 180 bottom
TP19  PAD~D  [TPC12]  182.41 71.4 90 bottom
TP20  PAD~D  [TPC12]  175.96 82.25 90 bottom
TP21  TP  [TP_C25]  166.62 63.09 90 top
TP22  PAD~D  [TPC12]  179.21 70.97 90 bottom
TP23  PAD~D  [TPC12]  176.7 71.71 90 bottom
TP24  TP  [TP_C25]  166.08 63.62 0 top
TP25  TP  [TP_C25]  168.24 58.16 0 top
TP26  TP  [TEST60]  207.07 82.4 180 bottom
TP27  TP  [TEST60]  203.28 83.66 180 bottom
TP28  TP  [TEST60]  206.85 83.09 180 bottom
TP29  TP  [TEST60]  208.67 81.82 180 bottom
TP30  TP  [TEST60]  203.15 84.36 180 bottom
TP31  TP  [TEST60]  207.81 81.79 180 bottom
TP32  TP  [TEST60]  203.24 82.96 180 bottom
TP33  TP  [TEST60]  206.85 81.71 180 bottom
TP34  TP  [TEST60]  202.38 81.93 180 bottom
TP35  TP  [TEST60]  208.98 90.79 0 top
TP36  TP  [TEST60]  209.98 90.8 0 top
TP37  TP  [TEST60]  212.72 90.7 225 top
TP38  TP  [TEST60]  212 91.41 225 top
TP39  TP  [TEST60]  67.05 69.26 180 bottom
TP40  TP  [TEST60]  69 69.49 180 bottom
TP41  TP  [TEST60]  66.01 69.26 180 bottom
TP42  TP  [TEST60]  201.47 81.48 180 bottom
TP43  TP  [TEST60]  203.41 81.33 180 bottom
TP44  TP  [TEST60]  209.18 84.04 180 bottom
TP45  TP  [TEST60]  208.7 83 180 bottom
TP46  TP  [TEST60]  208.19 83.95 180 bottom
TP47  TP  [TEST60]  207.84 83.03 180 bottom
TP48  TP  [TEST60]  166.33 74.96 0 top
TP49  TP  [TEST60]  165.32 74.94 0 top
TP50  TP  [TEST60]  170.89 75.71 180 bottom
TP51  TP  [TEST60]  172.8 75.68 180 bottom
TP52  TP  [TEST60]  209.32 82.4 180 bottom
TP53  TP  [TEST60]  210.2 82.46 180 bottom
TP54  TP  [TEST60]  209.62 81.71 180 bottom
TP55  TP  [TEST60]  209.88 83.42 180 bottom
TP56  TP  [TEST60]  32.23 84.83 0 top
TP57  TP  [TEST60]  32.72 85.75 0 top
TP58  TP  [TEST60]  33.89 85.7 0 top
TP59  TP  [TEST60]  51.64 19.71 180 bottom
TP63  TP  [TEST60]  56.82 69.39 180 bottom
TP65  TP  [TEST60]  205.14 87.54 180 bottom
TP66  TP  [TEST60]  205.26 83.72 180 bottom
TP69  TP  [TEST60]  210.86 83.09 180 bottom
TP70  TP  [TEST60]  211.72 83.06 180 bottom
TP71  TP  [TEST60]  172.22 77.63 180 bottom
TP72  TP  [TEST60]  172.79 69.4 180 bottom
TP73  TP  [TEST60]  171.58 70.23 180 bottom
U1  ICL U  [BGA91P35X99_1526N]  192.8 74.25 90 top
U2  RT8231A/B  [QFN40P300X300-20N]  114.19 54.2 90 bottom
U3  40+1_RT3613EB  [QFN40P500X500-40N_B]  223.9 102.79 90 bottom
U4  APL3512A/B  [SOT95P280-5N]  73.43 60.66 0 bottom
U5  SN74LVC1G08DCKR  [SOT65P190-5N]  150.54 60.18 180 top
U6  RT6543A  [QFN40P300X300-20N_A]  164.85 96.61 0 bottom
U7  RT6228CGQUF  [QFN72P300X300-20N]  91.78 86.21 0 top
U9  IT5570E-128/CX  [LQFP40P1600X1600-128N_A]  47.96 69.85 90 bottom
U10  SN74LVC1G08DCKR  [SOT65P190-5N]  127.48 94.41 0 bottom
U11  TPS2065  [SOT95P280-5N]  17.87 110.94 180 top
U13  SN74LVC1G07DCK  [SOT65P210-5N]  217.5 89.68 90 top
U14  APL3512A/B  [SOT95P280-5N]  123.17 89.7 180 bottom
U15  APL3526  [SON50P200X200-8N]  158.73 93.03 0 top
U16  APL3526  [SON50P200X200-8N]  162.73 51.75 0 bottom
U18  SN74LVC1G08DCKR  [SOT65P190-5N]  78.99 64.72 90 bottom
U20  RT6228AGQUF  [QFN72P300X300-20N]  123.37 81.01 180 top
U21  APL3526  [SON50P200X200-8N]  157.48 89.1 0 top
U22  TPS2065  [SOT95P280-5N]  39.71 109.32 0 top
U23  5_SN74LVC1G08DCKR  [SOT65P190-5N]  34.27 65.29 180 top
U24  RT6228AGQUF  [QFN72P300X300-20N]  146.78 95.88 0 top
U25  ALC256-CG  [QFN40P600X600-48N]  30.59 80.25 180 top
U27  TPS2065  [SOT95P280-5N]  54.37 99.94 90 bottom
U29  TPS2065  [SOT95P280-5N]  54.16 111.1 0 top
U30  RTL8111H  [QFN40P400X400-32AN]  72.12 70.73 270 bottom
U31  EG24A005S  [SOP99P996-24N]  73 82.38 90 top
U32  SN74LVC1G08DCKR  [SOT65P190-5N]  231.4 54.19 270 top
U33  SN74AHC1G08  [SOT65P210-5N]  231.54 46.38 270 top
U34  SN74LVC1G06DCK  [SOT65P210-5N]  41.19 61.54 180 top
U35  SN74LVC1G08DCKR  [SOT65P190-5N]  28.7 52.25 0 bottom
U36  MX25L8006EM2I-12G  [SOIC127P800-8N]  61.84 78.88 270 bottom
U36_S  SOCKET  [SKSOP8_127-1140X920]  61.84 79.29 180 bottom
U37  APW7228BRI-TRG  [TSSOP65P640-16AN]  27.56 47.48 0 bottom
U38  APL3517  [SOT95P280-3N]  61.94 110.07 0 top
U39  APL3526QBI-TRG  [SON50P200X200-8N]  56.96 11.35 180 bottom
U40  SN74LVC1G08DCKR  [SOT65P190-5N]  95.99 62.63 0 top
U41  TPS2065  [SOT95P280-5N]  122.02 50.47 180 bottom
U42  PS8625QFN56G  [QFN40P700X700-56AN]  52.33 25.38 180 bottom
U43  AT24C02A  [SOIC127P600-8N]  40.75 13.9 0 bottom
U44  AT24C02A  [SOIC127P600-8N]  50.94 13.52 180 bottom
U49  W25Q128JVSIQ  [SOIC127P540-8N]  134.06 64.89 0 top
U49_1  SOCKET  [SKSOP8_127-1140X920]  137.57 62.98 90 top
U50  SN74LVC1G07DCK  [SOT65P210-5N]  107.18 58.04 0 bottom
U51  APW8804QB  [TDFN50P300X300-10N]  146.85 78.09 180 top
U52  APL5930  [SOP127P600-9N]  216.94 10.59 180 bottom
U54  SN74LVC1G08DCKR  [SOT65P190-5N]  160.38 54.12 270 bottom
U55  APL3526  [SON50P200X200-8N]  147.32 72.38 270 top
U56  SN74LVC1G32DCKR  [SOT65P190-5N]  153.76 82.49 90 bottom
U57  SN74LVC1G32DCKR  [SOT65P190-5N]  65.27 27.06 180 bottom
UC1  2.2uF  [CC0603N]  165.36 68.18 180 top
X1  X3S038400FK1H  [OSC170P320X250-4N]  165.01 88.66 180 top
X2  X3S025000FK1H  [OSC170P320X250-4N]  63.41 71.09 90 bottom
X4  32.768KHZ  [SMY126X63]  173.85 59.21 0 bottom

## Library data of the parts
ACN1 CN4 CN6 CN8 = CN2+2-S
C1 C2 C4 C8 C9 C20-C25 C28-C42 C44-C50 C53 C54 C56-C59 C63 C68-C70 C75 C76 C86 C88 C104 C114 C118 C123 C125 C127-C132 C134-C137 C140 C144-C146 C158-C167 C169-C181 C183-C185 C188-C195 C197-C199 C201 C202 C205 C207 C209-C220 C222-C226 C228-C232 C235 C243-C254 C256-C278 C280 C281 C283-C290 C295-C331 C333-C336 C338 C340-C350 C352-C366 C376-C413 C415-C419 C421-C434 C436 C438-C441 C444-C446 C449-C458 C461-C464 C468-C472 C475-C488 C491 C493 C499-C502 C506 C507 C512-C520 C524 C526 C531 C532 C535-C537 C540-C546 C548-C550 C640-C642 C695-C701 C708-C727 C798 C877-C883 C885 C887-C908 C6036-C6041 C6056-C6058 C6112-C6126 C6128-C6140 C6147 C6148 C6154-C6156 C6158-C6160 LC1 PC1-PC4 PC6 PC8 PC12 PC13 PC16 PC18 PC21-PC26 PC28-PC30 PC39 PC42-PC45 PC48 PC50 PC52 PC54-PC59 PC61-PC69 = C
C3 C12 C60-C62 C66 C67 C73 C74 C77-C79 C81 C133 = C: signal model: C_CC0402N_220NF_220nF
C5 C10 C11 C13 C16-C18 C64 C65 C71 C72 C80 C90 C152-C155 C157 C168 C187 C196 C233 C234 = C: signal model: C_CC0402N_100NF_100NF
C6 C43 C51 C52 C55 C122 C124 C126 C143 C147 C200 C237-C242 C255 C279 C282 C291 C332 C337 C339 C351 C375 C414 C437 C443 C459 C467 C473 C474 C494 C495 C503 C509 C521 C522 C525 C534 C547 C634 C635 C702-C707 C884 C886 C3218 LC2 PC5 PC7 PC10 PC11 PC14 PC15 PC17 PC20 PC27 PC38 PC49 PC51 = C: alternate symbols: (T:CC0603N;B:CC0603M)
C7 CP2-CP5 CP7 CP10-CP13 CP18-CP20 PCP2 = C_P
C14 C15 C156 = C: alternate symbols: (T:CC0603N;B:CC0603M); signal model: C_CC0402N_100NF_100NF
C19 = C_P: signal model: C_CC0402N_100NF_100NF
C26 C27 C82-C85 C138 C139 C142 = C: signal model: C_CC0402N_0.01UF_0.01uF
C87 = C: signal model: C_CC0402N_0.22UF_0.22uF
C141 = C: alternate symbols: (T:CC0603N;B:CC0603M); signal model: C_CC0402N_0.01UF_0.01uF
C367-C374 = C: signal model: C_CC0402N_0.1U_0.1u
C420 C435 C442 C504 = C: alternate symbols: (T:CC1206N;B:CC1206M)
C465 = C#1_0: alternate symbols: (T:CC0603N;B:CC0603M); tolerance: 10%
C496 C497 C505 = C: alternate symbols: (T:CC1210N;B:CC1210M)
C6059-C6062 = C: signal model: C_CC0402N_0.1UF_0.1uF
C6064 = C_0: room: PCH
CN2 = CN10+2-S
CN3 = CN19+3-S
CN5 = BAT_CON_2
CN7 = CN-JACK-3
CN9 = CN-SATA-7+15+2-S
CN10 = CN75+2-J8
CN11 CN19 = CN-DDR4-260+2
CN12 = CN5+2-S
CN13 CN15 = CN4+2-S
CN14 = PCI-E_MINI_CARD_52+2_2
CN20 = CN8d_1
CN21 = CN40d+2_1
CN22 = CN75+2-S1_1
D1-D3 D7 D21 D22 D27 D28 D32-D38 D46 D50 D52-D57 D59-D62 D64 D65 = D
D4-D6 D16 = D_2PN: alternate symbols: (T:SOT95P280-3N;B:SOT95P280-3M)
D19 D20 D25 D66-D73 = D: alternate symbols: (T:sod2514n;B:SOD2514M)
D26 = D_2PN
D29 D45 D48 D49 = MC4_1: room: USB3.0
D58 = TVS
DR1 PR2 PR3 PR5-PR9 PR11 PR13 PR17 PR21 PR22 PR24-PR26 PR28-PR31 PR33-PR35 PR37 PR38 PR44-PR46 PR49-PR64 PR66-PR72 PR75-PR81 PR83 PR93-PR98 PR100-PR103 PR106-PR120 R3 R8-R10 R12 R15 R16 R18-R21 R23 R25 R27-R32 R34 R36 R37 R39-R41 R44 R46 R47 R49-R55 R57-R59 R65-R70 R72 R74-R80 R82 R83 R85 R86 R88 R90 R91 R93 R94 R96 R99 R101-R103 R105 R108 R110-R113 R115-R121 R125 R128 R129 R131-R135 R137-R144 R151 R153-R157 R160 R162 R163 R165 R167 R168 R171-R173 R175 R177 R179 R181 R184-R188 R194 R195 R198-R200 R202 R204-R207 R209-R214 R216 R217 R219 R224-R229 R231 R233 R235-R242 R246-R249 R251-R260 R262 R265 R267 R268 R271 R272 R276 R279 R280 R282 R284-R307 R309 R310 R313 R316-R318 R321 R322 R325-R330 R335 R338-R340 R345 R349-R357 R359-R361 R365 R369 R370 R372-R375 R377 R378 R381-R384 R387-R389 R391-R393 R396-R398 R400 R401 R404 R405 R408 R411 R412 R414-R420 R423-R425 R427 R433-R437 R440-R445 R447 R466 R476 R507 R508 R513 R517 R518 R520 R527 R529-R534 R536 R540 R544 R546-R548 R552-R554 R557-R559 R562-R566 R569-R571 R576 R581-R583 R588 R589 R591-R598 R600 R603-R608 R612 R619 R627-R629 R632-R637 R644 R647-R650 R653-R655 R664 R665 R679 R680 R721-R728 R733-R752 R781 R784 R785 R792 R794 R799 R801 R813 R814 R821-R825 R829-R832 R835 R836 R839-R843 R847-R852 R855-R858 R870 R873 R875 R882 R885 R888 R889 R892 R894-R900 R903-R909 R911 R916 R919 R925 R929 R931 R933 R934 R1389-R1391 R1393-R1400 = R
F1-F3 F5-F8 = FUSE
FB1 FB2 FB4 FB5 FB7 FB10 FB36 FB37 FB39 FB40 = FB: alternate symbols: (T:FB1206N;B:FB1206M)
FB3 FB9 FB11 FB12 FB18 LFB2 LFB3 = FB: alternate symbols: (T:FB0603N;B:FB0603M)
FB6 FB8 FB13-FB17 FB21 FB22 FB24-FB28 FB30 FB31 FB34 FB35 FB38 LFB1 = FB
FB41-FB43 = FB0603: User Part Number: HAMP; Tolerance: #TOL
FIL1-FIL11 FIL13-FIL18 = FIL4_DXW21BN7511TB
J1 J2 = CN-USB-9+2
J4 J5 = CN-USB-4+2
J7 J8 = CN-EARPHONE-5_15
J9 = CONN-3PIN
L2 L3 L6-L10 L18 LPM1-LPM3 LPM5 = L
LED2 = LED
LJ1 = RJ45_8+2
MARK1-MARK8 = MARK
MH1-MH13 = H
MQ1 = 7_SM7302ESKP
NS2 = NET_SHORT: User Part Number: ?
PR1 PR10 PR12 PR16 PR32 PR40 PR43 PR48 PR65 PR74 PR92 R5 R33 R35 R208 R220 R269 R390 = R_0: alternate symbols: (T:RC0603N;B:RC0603M)
